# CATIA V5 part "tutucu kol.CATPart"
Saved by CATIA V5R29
Part number: tutucu kol
Revision: HERHANG?
Definition: B??MEYEN
Nomenclature: tutucu kol
Source: Unknown
Bounding box of the stored display mesh (mm): x -0.144 to 377, y -366.554 to 0, z 22.284 to 147.443
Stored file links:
  C:\가치같이\SmartFactory_Freeze dryer\tutucu kol.CATPart
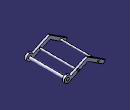
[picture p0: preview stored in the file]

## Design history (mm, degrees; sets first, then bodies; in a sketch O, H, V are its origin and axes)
Body1 "Y?seklik-Ekstr?yon1" (main body)
  Solid1: solid without history
Body2 "Y?seklik-Ekstr?yon4"
  Solid2: solid without history
Body3 "Y?seklik-Ekstr?yon5[1]"
  Solid3: solid without history
Body4 "Y?seklik-Ekstr?yon5[2]"
  Solid4: solid without history
Body5 "Y?seklik-Ekstr?yon5[3]"
  Solid5: solid without history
